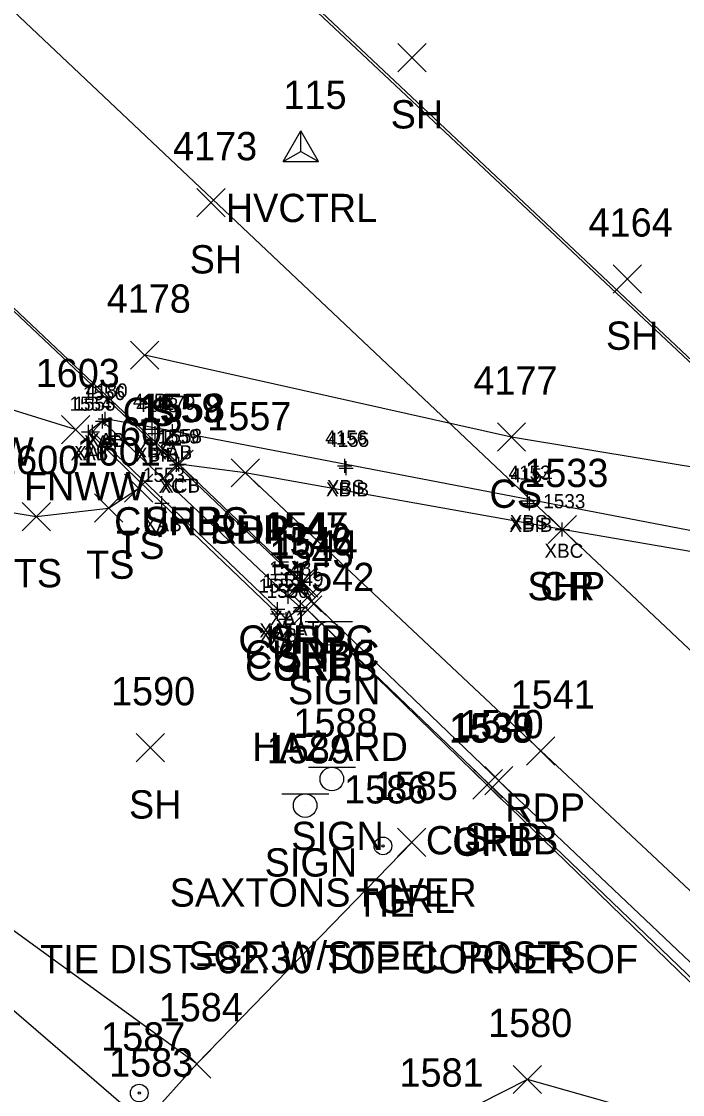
# Model space of a CAD drawing. Extents: x 1647574 to 1652703, y 212895 to 228670.
# Drawn here: x 1649179.8 to 1649226.5, y 226954.6 to 227030.4 of the extents above; entities that cross this region are included whole.
import ezdxf

# ---------------------------------------------------------------- set-up
doc = ezdxf.new("R2010")
doc.units = 0
for name, color, linetype in [('B_A', 7, 'Continuous'), ('B_I', 7, 'Continuous'), ('B_TIC', 7, 'Continuous'), ('BDC', 7, 'Continuous'), ('BELB', 7, 'Continuous'), ('BSUBM', 7, 'Continuous'), ('C_A', 7, 'Continuous'), ('C_C', 7, 'Continuous'), ('C_I', 7, 'Continuous'), ('CBP', 7, 'Continuous'), ('CPSM', 7, 'Continuous'), ('L_A', 7, 'Continuous'), ('L_I', 7, 'Continuous'), ('L_TIC', 7, 'Continuous'), ('LELB', 7, 'Continuous'), ('LFNC', 7, 'Continuous'), ('P_A', 7, 'Continuous'), ('P_I', 7, 'Continuous'), ('P_TIC', 7, 'Continuous'), ('PET', 7, 'Continuous'), ('PRC', 7, 'Continuous'), ('PSP', 7, 'Continuous'), ('R_A', 7, 'Continuous'), ('R_C', 7, 'Continuous'), ('R_I', 7, 'Continuous'), ('R_TIC', 7, 'Continuous'), ('RC', 7, 'Continuous'), ('RGR', 7, 'Continuous'), ('S_A', 7, 'Continuous'), ('S_C', 7, 'Continuous'), ('S_I', 7, 'Continuous'), ('SSGN', 7, 'Continuous')]:
    doc.layers.add(name, color=color, linetype=linetype)

msp = doc.modelspace()

# ---------------------------------------------------------------- linework, layer by layer
at = {"layer": 'B_TIC'}
for p, q in [((1649185.728, 227002.334), (1649185.804, 227002.334)), ((1649185.535, 227002.155), (1649185.61, 227002.155)), ((1649185.535, 227002.155), (1649185.61, 227002.155)), ((1649189.043, 227001.602), (1649189.119, 227001.602)), ((1649184.557, 227001.401), (1649184.633, 227001.401)), ((1649184.84, 227001.406), (1649184.915, 227001.406)), ((1649189.273, 227001.301), (1649189.348, 227001.301)), ((1649190.483, 227001.463), (1649190.559, 227001.463)), ((1649190.781, 226999.084), (1649190.856, 226999.084)), ((1649190.947, 226999.114), (1649191.023, 226999.114)), ((1649202.665, 226999.007), (1649202.741, 226999.007)), ((1649202.767, 226998.843), (1649202.842, 226998.843)), ((1649189.746, 226996.37), (1649189.822, 226996.37)), ((1649215.596, 226996.524), (1649215.671, 226996.524)), ((1649215.731, 226996.341), (1649215.807, 226996.341)), ((1649218.049, 226994.506), (1649218.125, 226994.506)), ((1649198.678, 226989.761), (1649198.754, 226989.761)), ((1649198.678, 226989.761), (1649198.754, 226989.761)), ((1649197.925, 226988.875), (1649198, 226988.875)), ((1649199.54, 226989.006), (1649199.615, 226989.006)), ((1649197.915, 226988.542), (1649197.99, 226988.542)), ((1649198.532, 226988.17), (1649198.607, 226988.17))]:
    msp.add_line(p, q, dxfattribs=at)
for points in [[(1649185.225, 227002.334), (1649186.225, 227002.334)], [(1649185.532, 227001.655), (1649185.532, 227002.655)], [(1649185.532, 227001.655), (1649185.532, 227002.655)], [(1649185.725, 227001.834), (1649185.725, 227002.834)], [(1649184.554, 227000.901), (1649184.554, 227001.901)], [(1649184.836, 227000.906), (1649184.836, 227001.906)], [(1649185.032, 227002.155), (1649186.032, 227002.155)], [(1649185.032, 227002.155), (1649186.032, 227002.155)], [(1649188.54, 227001.602), (1649189.54, 227001.602)], [(1649189.04, 227001.102), (1649189.04, 227002.102)], [(1649189.269, 227000.801), (1649189.269, 227001.801)], [(1649190.48, 227000.963), (1649190.48, 227001.963)], [(1649184.054, 227001.401), (1649185.054, 227001.401)], [(1649184.336, 227001.406), (1649185.336, 227001.406)], [(1649188.769, 227001.301), (1649189.769, 227001.301)], [(1649189.98, 227001.463), (1649190.98, 227001.463)], [(1649190.777, 226998.584), (1649190.777, 226999.584)], [(1649190.944, 226998.614), (1649190.944, 226999.614)], [(1649202.662, 226998.507), (1649202.662, 226999.507)], [(1649202.763, 226998.343), (1649202.763, 226999.343)], [(1649190.277, 226999.084), (1649191.277, 226999.084)], [(1649190.444, 226999.114), (1649191.444, 226999.114)], [(1649202.162, 226999.007), (1649203.162, 226999.007)], [(1649202.263, 226998.843), (1649203.263, 226998.843)], [(1649215.592, 226996.024), (1649215.592, 226997.024)], [(1649189.243, 226996.37), (1649190.243, 226996.37)], [(1649189.743, 226995.87), (1649189.743, 226996.87)], [(1649215.092, 226996.524), (1649216.092, 226996.524)], [(1649215.228, 226996.341), (1649216.228, 226996.341)], [(1649215.728, 226995.841), (1649215.728, 226996.841)], [(1649218.046, 226994.006), (1649218.046, 226995.006)], [(1649217.546, 226994.506), (1649218.546, 226994.506)], [(1649198.675, 226989.261), (1649198.675, 226990.261)], [(1649198.675, 226989.261), (1649198.675, 226990.261)], [(1649198.175, 226989.761), (1649199.175, 226989.761)], [(1649198.175, 226989.761), (1649199.175, 226989.761)], [(1649199.536, 226988.506), (1649199.536, 226989.506)], [(1649197.421, 226988.875), (1649198.421, 226988.875)], [(1649197.911, 226988.042), (1649197.911, 226989.042)], [(1649197.921, 226988.375), (1649197.921, 226989.375)], [(1649199.036, 226989.006), (1649200.036, 226989.006)], [(1649197.411, 226988.542), (1649198.411, 226988.542)], [(1649198.028, 226988.17), (1649199.028, 226988.17)], [(1649198.528, 226987.67), (1649198.528, 226988.67)]]:
    msp.add_lwpolyline(points, dxfattribs=at)
at = {"layer": 'BDC'}
for points in [[(1649190.777, 226999.084), (1649140.468, 227046.558), (1649090.33, 227093.733), (1649025.71, 227154.751), (1648968.186, 227208.898), (1648910.789, 227263.155), (1648860.431, 227310.794), (1648808.664, 227359.741)], [(1649190.944, 226999.114), (1649140.59, 227046.719), (1649090.397, 227093.864), (1649025.741, 227154.791), (1648968.355, 227208.988), (1648910.836, 227263.351), (1648860.59, 227310.809), (1648808.767, 227359.651)], [(1649243.4, 226991.008), (1649194.892, 227036.57), (1649144.766, 227083.811), (1649080.187, 227144.73), (1649023.114, 227198.758), (1648965.385, 227253.071), (1648915.007, 227300.535), (1648862.79, 227349.772)], [(1649243.526, 226991.095), (1649195.071, 227036.681), (1649144.945, 227083.846), (1649080.275, 227144.791), (1649023.25, 227198.713), (1648965.389, 227253.216), (1648915.176, 227300.61), (1648862.963, 227349.863)]]:
    msp.add_lwpolyline(points, dxfattribs=at)
at = {"layer": 'BELB'}
msp.add_lwpolyline([(1649218.046, 226994.506), (1649168.124, 227041.655), (1649117.675, 227088.79), (1649053.801, 227149.566), (1648996.598, 227203.697), (1648938.733, 227258.119), (1648889.571, 227305.276), (1648838.072, 227353.54)], dxfattribs=at)
at = {"layer": 'BSUBM'}
for points in [[(1649185.725, 227002.334), (1649184.554, 227001.401)], [(1649245.187, 226990.996), (1649239.833, 226991.986), (1649190.48, 227001.463), (1649185.725, 227002.334)], [(1649198.675, 226989.761), (1649199.536, 226989.006), (1649198.528, 226988.17), (1649197.921, 226988.875), (1649184.836, 227001.406), (1649185.532, 227002.155)], [(1649198.675, 226989.761), (1649185.532, 227002.155)], [(1649197.911, 226988.542), (1649189.743, 226996.37), (1649184.554, 227001.401)]]:
    msp.add_lwpolyline(points, dxfattribs=at)
at = {"layer": 'CBP'}
for centre, radius in [((1649205.365, 226972.145), 0.625), ((1649205.365, 226972.145), 0.0833), ((1649188.132, 226954.678), 0.625), ((1649188.132, 226954.678), 0.0833)]:
    msp.add_circle(centre, radius, dxfattribs=at)
at = {"layer": 'CPSM'}
for p, q in [((1649198.311, 227020.51), (1649199.561, 227022.675)), ((1649200.811, 227020.51), (1649199.561, 227022.675)), ((1649199.561, 227021.231), (1649199.561, 227022.675)), ((1649198.311, 227020.51), (1649199.561, 227021.231)), ((1649199.561, 227021.231), (1649199.561, 227021.231)), ((1649199.561, 227021.231), (1649200.811, 227020.51)), ((1649198.311, 227020.51), (1649200.811, 227020.51))]:
    msp.add_line(p, q, dxfattribs=at)
at = {"layer": 'L_TIC'}
for points in [[(1649206.423, 227026.848), (1649208.423, 227028.848)], [(1649208.423, 227026.848), (1649206.423, 227028.848)], [(1649192.214, 227016.601), (1649194.214, 227018.601)], [(1649194.214, 227016.601), (1649192.214, 227018.601)], [(1649221.643, 227011.206), (1649223.643, 227013.206)], [(1649223.643, 227011.206), (1649221.643, 227013.206)], [(1649187.525, 227005.828), (1649189.525, 227007.828)], [(1649189.525, 227005.828), (1649187.525, 227007.828)], [(1649182.632, 227000.567), (1649184.632, 227002.567)], [(1649184.632, 227000.567), (1649182.632, 227002.567)], [(1649213.453, 227000.037), (1649215.453, 227002.037)], [(1649215.453, 227000.037), (1649213.453, 227002.037)], [(1649187.097, 226996.429), (1649189.097, 226998.429)], [(1649189.097, 226996.429), (1649187.097, 226998.429)], [(1649184.969, 226995.023), (1649186.969, 226997.023)], [(1649186.969, 226995.023), (1649184.969, 226997.023)], [(1649179.85, 226994.424), (1649181.85, 226996.424)], [(1649181.85, 226994.424), (1649179.85, 226996.424)], [(1649187.917, 226978.079), (1649189.917, 226980.079)], [(1649189.917, 226978.079), (1649187.917, 226980.079)], [(1649191.206, 226955.741), (1649193.206, 226957.741)], [(1649193.206, 226955.741), (1649191.206, 226957.741)], [(1649214.582, 226954.638), (1649216.582, 226956.638)], [(1649216.582, 226954.638), (1649214.582, 226956.638)]]:
    msp.add_lwpolyline(points, dxfattribs=at)
at = {"layer": 'LELB'}
for points in [[(1649601.717, 226556.302), (1649565.565, 226590.442), (1649531.933, 226623.516), (1649496.555, 226657.42), (1649463.007, 226688.129), (1649429.087, 226720.608), (1649397.934, 226750.553), (1649357.866, 226787.133), (1649324.24, 226819.114), (1649290.454, 226852.029), (1649264.596, 226876.987), (1649236.486, 226903.171), (1649212.259, 226932.025), (1649172.545, 226966.257), (1649148.692, 226987.126), (1649125.302, 227007.744), (1649116.811, 227012.433), (1649123.681, 227011.795), (1649139.116, 227006.117), (1649163.745, 226998.25), (1649180.85, 226995.424), (1649185.969, 226996.023), (1649188.097, 226997.429)], [(1649192.206, 226956.741), (1649176.07, 226968.448), (1649150.815, 226988.424), (1649123.681, 227011.795)], [(1649239.025, 226996.95), (1649214.453, 227001.037), (1649188.525, 227006.828)], [(1649593.121, 226613.007), (1649554.759, 226645.438), (1649523.047, 226677.152), (1649485.111, 226713.45), (1649453.016, 226743.38), (1649420.607, 226775.732), (1649384.192, 226809.438), (1649346.962, 226843.75), (1649308.842, 226878.401), (1649286.162, 226899.193), (1649254.425, 226924.586), (1649231.459, 226951.134), (1649215.582, 226955.638), (1649208.659, 226952.13), (1649203.071, 226945.741)]]:
    msp.add_lwpolyline(points, dxfattribs=at)
at = {"layer": 'LFNC'}
msp.add_lwpolyline([(1649183.632, 227001.567), (1649175.712, 227004.03), (1649162.879, 227008.351), (1649140.743, 227015.822), (1649121.817, 227022.228), (1649109.537, 227025.911), (1649101.581, 227028.294)], dxfattribs=at)
at = {"layer": 'P_TIC'}
for points in [[(1649189.944, 226998.114), (1649191.944, 227000.114)], [(1649191.944, 226998.114), (1649189.944, 227000.114)], [(1649189.944, 226998.114), (1649191.944, 227000.114)], [(1649191.944, 226998.114), (1649189.944, 227000.114)], [(1649194.635, 226997.512), (1649196.635, 226999.512)], [(1649196.635, 226997.512), (1649194.635, 226999.512)], [(1649194.635, 226997.512), (1649196.635, 226999.512)], [(1649196.635, 226997.512), (1649194.635, 226999.512)], [(1649217.046, 226993.506), (1649219.046, 226995.506)], [(1649219.046, 226993.506), (1649217.046, 226995.506)], [(1649217.046, 226993.506), (1649219.046, 226995.506)], [(1649219.046, 226993.506), (1649217.046, 226995.506)], [(1649198.757, 226989.723), (1649200.757, 226991.723)], [(1649200.757, 226989.723), (1649198.757, 226991.723)], [(1649199.333, 226988.449), (1649201.333, 226990.449)], [(1649201.333, 226988.449), (1649199.333, 226990.449)], [(1649215.518, 226977.854), (1649217.518, 226979.854)], [(1649217.518, 226977.854), (1649215.518, 226979.854)], [(1649212.557, 226975.755), (1649214.557, 226977.755)], [(1649214.557, 226975.755), (1649212.557, 226977.755)]]:
    msp.add_lwpolyline(points, dxfattribs=at)
at = {"layer": 'PET'}
msp.add_lwpolyline([(1649598.447, 226617.545), (1649561.337, 226652.897), (1649529.432, 226682.639), (1649490.939, 226719.165), (1649459.141, 226749.195), (1649424.851, 226781.605), (1649390.384, 226814.476), (1649353.234, 226849.636), (1649316.21, 226884.712), (1649282.402, 226916.906), (1649254.366, 226943.23), (1649236.042, 226960.59), (1649216.518, 226978.854), (1649195.635, 226998.512)], dxfattribs=at)
at = {"layer": 'PRC'}
msp.add_lwpolyline([(1649606.746, 226626.949), (1649570.25, 226661.64), (1649538.472, 226691.377), (1649499.095, 226728.539), (1649467.902, 226758.267), (1649433.876, 226790.68), (1649398.711, 226823.762), (1649362.825, 226857.801), (1649324.194, 226893.362), (1649291.595, 226925.623), (1649262.783, 226952.365), (1649218.046, 226994.506)], dxfattribs=at)
at = {"layer": 'PSP'}
for points in [[(1649595.64, 226615.02), (1649558.326, 226650.152), (1649527.094, 226680.38), (1649488.241, 226717.057), (1649456.656, 226746.86), (1649422.676, 226779.059), (1649387.283, 226812.318), (1649351.052, 226846.643), (1649313.214, 226882.308), (1649279.734, 226913.94), (1649251.2, 226941.222), (1649233.382, 226957.973), (1649213.557, 226976.755), (1649200.333, 226989.449), (1649199.757, 226990.723), (1649190.944, 226999.114)], [(1649606.954, 226655.869), (1649570.92, 226690.009), (1649534.663, 226724.213), (1649502.869, 226754.778), (1649467.983, 226787.829), (1649433.218, 226820.152), (1649395.449, 226855.859), (1649369.288, 226880.337), (1649338.69, 226908.034), (1649304.509, 226937.469), (1649274.576, 226964.092), (1649261.765, 226975.072), (1649262.113, 226976.252), (1649259.135, 226977.145), (1649257.676, 226977.615), (1649243.4, 226991.008), (1649239.829, 226990.769), (1649218.046, 226994.506), (1649195.635, 226998.512), (1649190.944, 226999.114)]]:
    msp.add_lwpolyline(points, dxfattribs=at)
at = {"layer": 'R_TIC'}
for points in [[(1649189.777, 226998.084), (1649191.777, 227000.084)], [(1649191.777, 226998.084), (1649189.777, 227000.084)], [(1649198.561, 226989.727), (1649200.561, 226991.727)], [(1649200.561, 226989.727), (1649198.561, 226991.727)], [(1649198.561, 226989.727), (1649200.561, 226991.727)], [(1649200.561, 226989.727), (1649198.561, 226991.727)], [(1649199.024, 226988.677), (1649201.024, 226990.677)], [(1649201.024, 226988.677), (1649199.024, 226990.677)], [(1649199.035, 226987.827), (1649201.035, 226989.827)], [(1649201.035, 226987.827), (1649199.035, 226989.827)], [(1649199.035, 226987.827), (1649201.035, 226989.827)], [(1649201.035, 226987.827), (1649199.035, 226989.827)], [(1649211.722, 226975.444), (1649213.722, 226977.444)], [(1649213.722, 226975.444), (1649211.722, 226977.444)], [(1649211.817, 226975.547), (1649213.817, 226977.547)], [(1649213.817, 226975.547), (1649211.817, 226977.547)], [(1649206.404, 226971.395), (1649208.404, 226973.395)], [(1649208.404, 226971.395), (1649206.404, 226973.395)], [(1649191.206, 226955.741), (1649193.206, 226957.741)], [(1649193.206, 226955.741), (1649191.206, 226957.741)]]:
    msp.add_lwpolyline(points, dxfattribs=at)
at = {"layer": 'RC'}
for points in [[(1649199.561, 226990.727), (1649190.777, 226999.084)], [(1649200.024, 226989.677), (1649199.561, 226990.727)], [(1649232.672, 226957.525), (1649212.817, 226976.547), (1649200.035, 226988.827)]]:
    msp.add_lwpolyline(points, dxfattribs=at)
at = {"layer": 'RGR'}
for points in [[(1649553.69, 226650.38), (1649526.882, 226680.036), (1649487.893, 226716.68), (1649456.338, 226746.594), (1649422.283, 226778.819), (1649386.822, 226812.076), (1649350.556, 226846.464), (1649313.098, 226882.032), (1649279.454, 226913.718), (1649250.854, 226941.012), (1649232.603, 226957.179), (1649212.722, 226976.444), (1649200.035, 226988.827)], [(1649188.696, 226952.843), (1649192.206, 226956.741), (1649207.404, 226972.395)]]:
    msp.add_lwpolyline(points, dxfattribs=at)
at = {"layer": 'SSGN'}
for p, q in [((1649199.868, 226988.006), (1649203.202, 226988.006)), ((1649201.515, 226987.172), (1649201.515, 226987.172)), ((1649200.102, 226977.707), (1649203.435, 226977.707)), ((1649201.749, 226976.873), (1649201.749, 226976.873)), ((1649198.217, 226975.831), (1649201.551, 226975.831)), ((1649199.864, 226974.998), (1649199.864, 226974.998))]:
    msp.add_line(p, q, dxfattribs=at)
for centre in [(1649201.515, 226987.172), (1649201.749, 226976.873), (1649199.864, 226974.998)]:
    msp.add_circle(centre, 0.833, dxfattribs=at)

# ---------------------------------------------------------------- texts
at = {"layer": 'B_A'}
for s, p in [('XAT', (1649184.236, 227000.155)), ('XAT', (1649184.236, 227000.155)), ('XAB', (1649184.445, 227000.334)), ('XAB', (1649183.274, 226999.401)), ('XAT', (1649183.541, 226999.406)), ('XBS', (1649187.78, 226999.602)), ('XBIB', (1649187.84, 226999.301)), ('XAB', (1649189.201, 226999.463)), ('XCT', (1649189.498, 226997.084)), ('XCB', (1649189.68, 226997.114)), ('XBIB', (1649201.334, 226996.843)), ('XBS', (1649201.402, 226997.007)), ('XBS', (1649214.332, 226994.524)), ('XAB', (1649188.463, 226994.37)), ('XBIB', (1649214.299, 226994.341)), ('XBC', (1649216.782, 226992.506)), ('XAT', (1649197.379, 226987.761)), ('XAT', (1649197.379, 226987.761)), ('XAT', (1649198.241, 226987.006)), ('XAT', (1649196.626, 226986.875)), ('XAB', (1649196.632, 226986.542)), ('XAT', (1649197.233, 226986.17))]:
    msp.add_text(s, height=1, dxfattribs=at).set_placement(p)
at = {"layer": 'B_I'}
for s, p in [('1556', (1649184.158, 227003.655)), ('1556', (1649184.158, 227003.655)), ('4180', (1649184.335, 227003.834)), ('1554', (1649183.207, 227002.901)), ('1555', (1649183.49, 227002.906)), ('4157', (1649187.693, 227003.102)), ('4179', (1649189.13, 227002.963)), ('4158', (1649187.923, 227002.801)), ('1559', (1649189.427, 227000.584)), ('1558', (1649189.597, 227000.614)), ('4156', (1649201.288, 227000.507)), ('4155', (1649201.417, 227000.343)), ('1553', (1649188.397, 226997.87)), ('4153', (1649214.246, 226998.024)), ('4154', (1649214.381, 226997.841)), ('1533', (1649216.7, 226996.006)), ('1548', (1649197.328, 226991.261)), ('1548', (1649197.328, 226991.261)), ('1552', (1649196.565, 226990.042)), ('1551', (1649196.859, 226990.375)), ('1549', (1649198.186, 226990.506)), ('1550', (1649197.139, 226989.67))]:
    msp.add_text(s, height=1, dxfattribs=at).set_placement(p)
at = {"layer": 'C_A'}
for s, p in [('HVCTRL', (1649194.254, 227016.231)), ('TIE', (1649203.444, 226967.145))]:
    msp.add_text(s, height=2, dxfattribs=at).set_placement(p)
at = {"layer": 'C_C'}
msp.add_text('TIE DIST=82.30 TOP CORNER OF', height=2, dxfattribs=at).set_placement((1649181.122, 226963.145))
at = {"layer": 'C_I'}
for s, p in [('115', (1649198.333, 227024.231)), ('1586', (1649202.617, 226975.145)), ('1587', (1649185.44, 226957.678))]:
    msp.add_text(s, height=2, dxfattribs=at).set_placement(p)
at = {"layer": 'L_A'}
for s, p in [('SH', (1649205.911, 227022.848)), ('SH', (1649191.702, 227012.601)), ('SH', (1649221.131, 227007.206)), ('CS', (1649186.966, 227001.828)), ('FNWW', (1649172.058, 226999.03)), ('FNWW', (1649179.978, 226996.567)), ('CS', (1649212.894, 226996.037)), ('TS', (1649186.507, 226992.429)), ('TS', (1649184.378, 226991.023)), ('TS', (1649179.26, 226990.424)), ('SH', (1649187.406, 226974.079))]:
    msp.add_text(s, height=2, dxfattribs=at).set_placement(p)
at = {"layer": 'L_I'}
for s, p in [('4173', (1649190.521, 227020.601)), ('4164', (1649219.903, 227015.206)), ('4178', (1649185.833, 227009.828)), ('1603', (1649180.813, 227004.567)), ('4177', (1649211.76, 227004.037)), ('1602', (1649185.279, 227000.429)), ('1601', (1649183.717, 226999.023)), ('1600', (1649177.945, 226998.424)), ('1590', (1649186.138, 226982.079)), ('1584', (1649189.513, 226959.741)), ('1580', (1649212.802, 226958.638)), ('1581', (1649206.533, 226955.13))]:
    msp.add_text(s, height=2, dxfattribs=at).set_placement(p)
at = {"layer": 'P_A'}
for s, p in [('SHP', (1649188.479, 226994.114)), ('SHP', (1649188.479, 226994.114)), ('SHP', (1649193.17, 226993.512)), ('RDP', (1649193.123, 226993.512)), ('SHP', (1649215.581, 226989.506)), ('CR', (1649216.479, 226989.506)), ('SHP', (1649197.292, 226985.723)), ('SHP', (1649197.869, 226984.449)), ('RDP', (1649214.006, 226973.854)), ('SHP', (1649211.093, 226971.755))]:
    msp.add_text(s, height=2, dxfattribs=at).set_placement(p)
at = {"layer": 'P_I'}
for s, p in [('1558', (1649188.251, 227002.114)), ('1558', (1649188.251, 227002.114)), ('1557', (1649192.942, 227001.512)), ('1557', (1649192.942, 227001.512)), ('1533', (1649215.353, 226997.506)), ('1533', (1649215.353, 226997.506)), ('1545', (1649197.064, 226993.723)), ('1544', (1649197.641, 226992.449)), ('1541', (1649214.392, 226981.854)), ('1540', (1649210.778, 226979.755))]:
    msp.add_text(s, height=2, dxfattribs=at).set_placement(p)
at = {"layer": 'R_A'}
for s, p in [('CURBG', (1649186.36, 226994.084)), ('CURBC', (1649195.144, 226985.727)), ('CURBG', (1649195.144, 226985.727)), ('CURBC', (1649195.607, 226984.677)), ('CURBB', (1649195.618, 226983.827)), ('GRL', (1649197.579, 226983.827)), ('CURBB', (1649208.4, 226971.547)), ('GRL', (1649210.265, 226971.444)), ('GRL', (1649204.947, 226967.395))]:
    msp.add_text(s, height=2, dxfattribs=at).set_placement(p)
at = {"layer": 'R_C'}
msp.add_text('SGR W/STEEL POSTS', height=2, dxfattribs=at).set_placement((1649191.609, 226963.395))
at = {"layer": 'R_I'}
for s, p in [('1559', (1649188.077, 227002.084)), ('1547', (1649196.868, 226993.727)), ('1547', (1649196.868, 226993.727)), ('1546', (1649197.276, 226992.677)), ('1543', (1649197.343, 226991.827)), ('1543', (1649197.343, 226991.827)), ('1538', (1649210.029, 226979.444)), ('1539', (1649210.116, 226979.547)), ('1585', (1649204.711, 226975.395)), ('1584', (1649189.513, 226959.741)), ('1583', (1649186.003, 226955.843))]:
    msp.add_text(s, height=2, dxfattribs=at).set_placement(p)
at = {"layer": 'S_A'}
for p in [(1649198.653, 226982.152), (1649198.887, 226971.853), (1649197.002, 226969.978)]:
    msp.add_text('SIGN', height=2, dxfattribs=at).set_placement(p)
at = {"layer": 'S_C'}
for s, p in [('HAZARD', (1649196.133, 226978.152)), ('SAXTONS RIVER', (1649190.289, 226967.853))]:
    msp.add_text(s, height=2, dxfattribs=at).set_placement(p)
at = {"layer": 'S_I'}
for s, p in [('1542', (1649198.803, 226990.152)), ('1588', (1649199.037, 226979.853)), ('1589', (1649197.144, 226977.978))]:
    msp.add_text(s, height=2, dxfattribs=at).set_placement(p)

doc.saveas('drawing.dxf')
